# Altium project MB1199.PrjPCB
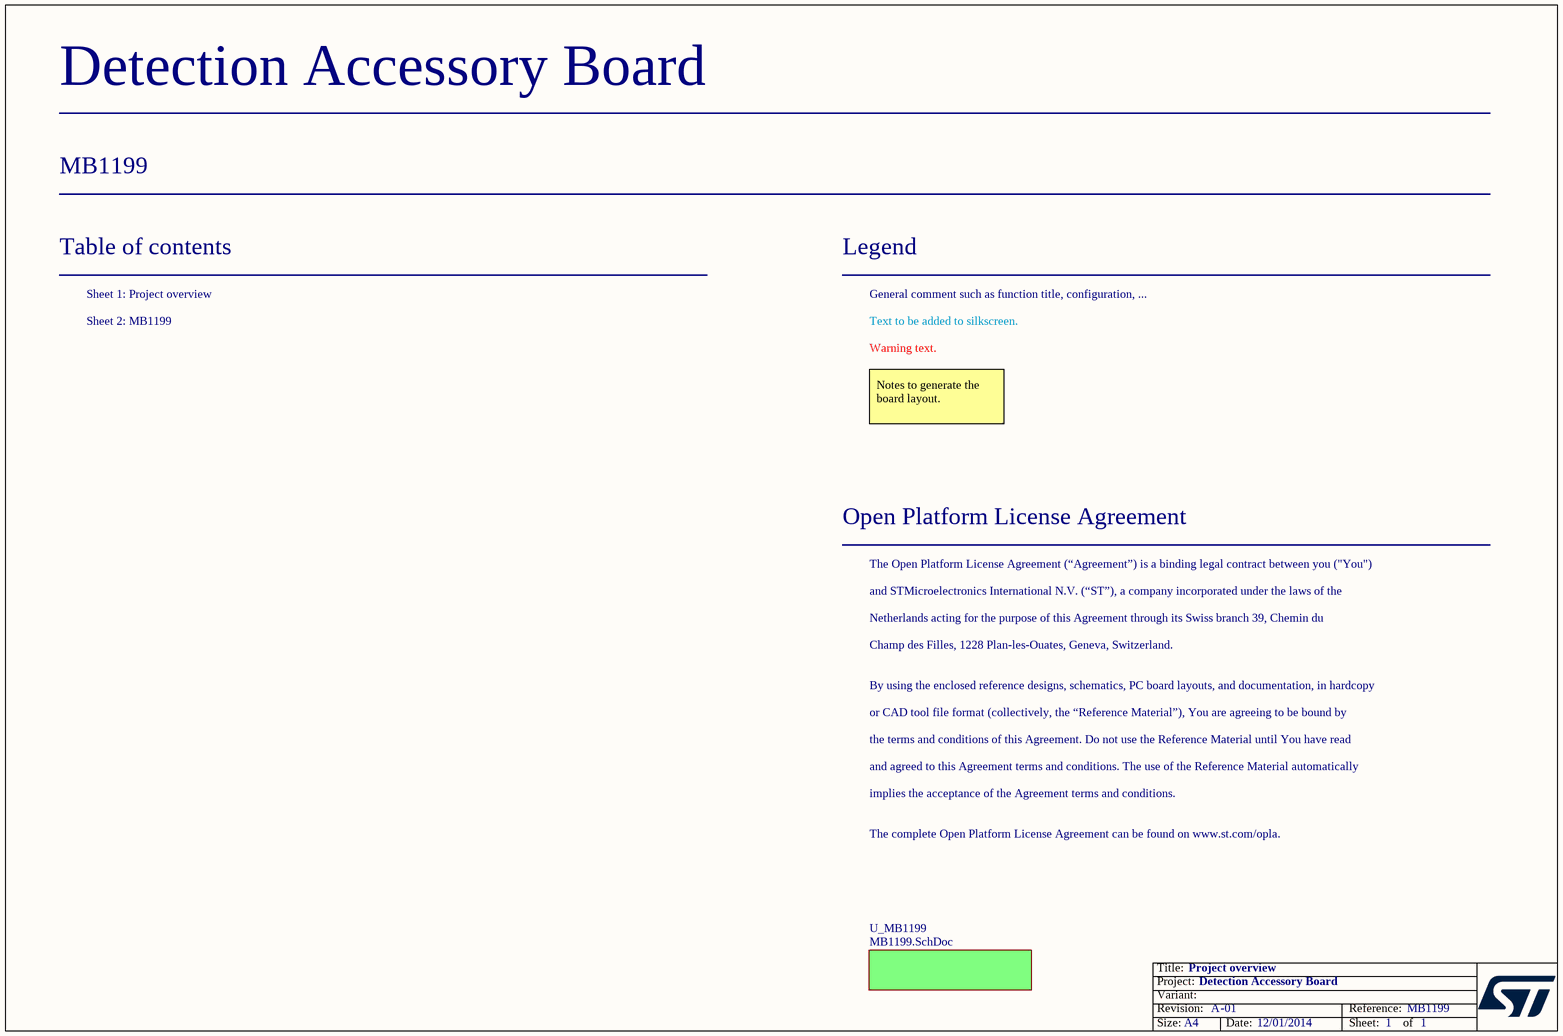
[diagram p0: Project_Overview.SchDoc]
Board_Assembly_Revision: 01; Board_Document_Date: 12/01/2014; Board_Name: Detection Accessory Board; Board_PCB_Revision: A; Board_Reference: MB1199
2 sheets, 1 parts. Net scope: global (net labels, ports and power ports of the same name join across sheets).
Board file: MB1199.PcbDoc
Sheets:
  Project_Overview.SchDoc
    U_MB1199 = MB1199.SchDoc

## Sheet Project_Overview.SchDoc: Project overview
size A4; Date: Not used; ApprovedBy: Not used; CheckedBy: Not used; Author: Not used; CompanyName: STMicroelectronics; DrawnBy: Not used; Engineer: Not used; Organization: Not used; Address1: Not used; Address2: Not used; Address3: Not used; Address4: Not used; DocumentNumber: Not used; Revision: Not used; SheetNumber: 1; SheetTotal: 1

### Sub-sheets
U_MB1199 = MB1199.SchDoc: no entries

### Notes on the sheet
- Table of contents
- Sheet 1: Project overview
- Legend
- General comment such as function title, configuration, ...
- Sheet 2: MB1199
- Text to be added to silkscreen.
- Warning text.
- Notes to generate the board layout.
- Open Platform License Agreement
- The Open Platform License Agreement (“Agreement”) is a binding legal contract between you ("You")
- and STMicroelectronics International N.V. (“ST”), a company incorporated under the laws of the
- Netherlands acting for the purpose of this Agreement through its Swiss branch 39, Chemin du
- Champ des Filles, 1228 Plan-les-Ouates, Geneva, Switzerland.
- By using the enclosed reference designs, schematics, PC board layouts, and documentation, in hardcopy
- or CAD tool file format (collectively, the “Reference Material”), You are agreeing to be bound by
- the terms and conditions of this Agreement. Do not use the Reference Material until You have read
- and agreed to this Agreement terms and conditions. The use of the Reference Material automatically
- implies the acceptance of the Agreement terms and conditions.
- The complete Open Platform License Agreement can be found on www.st.com/opla.

## Sheet MB1199.SchDoc: MB1199
size A4; Date: 01-DEC-2013; CompanyName: STMicroelectronics; Organization: Microcontrollers Division; Address1: 12, Rue Jules HOROWITZ; Address2: 38019 Grenoble; Address3: FRANCE; DocumentNumber: 2; Revision: A-01; SheetNumber: 2; SheetTotal: 2; Project: Detection Accessory
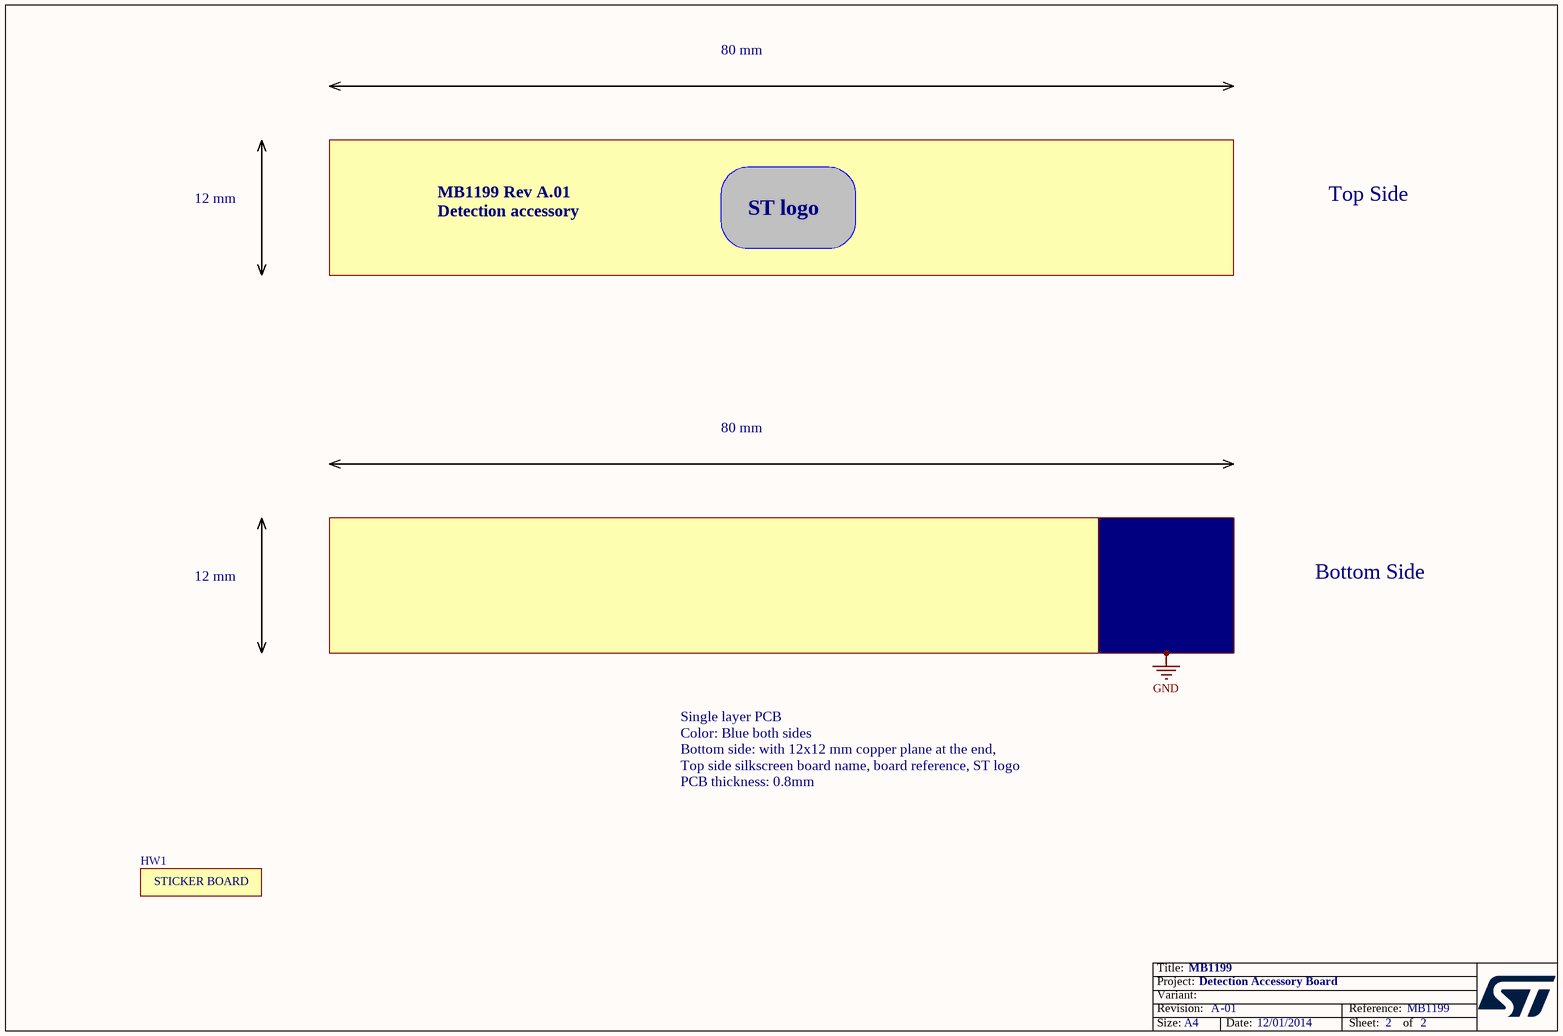
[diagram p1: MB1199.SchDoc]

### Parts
HW1  STICKER_BOARD  (value not drawn)  (no BOM)

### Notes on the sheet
- 80 mm
- 12 mm
- ST logo
- Top Side
- MB1199 Rev A.01
  Detection accessory
- Bottom Side
- Single layer PCB
  Color: Blue both sides
  Bottom side: with 12x12 mm copper plane at the end,
  Top side silkscreen board name, board reference, ST logo
  PCB thickness: 0.8mm

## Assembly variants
Default: all parts fitted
